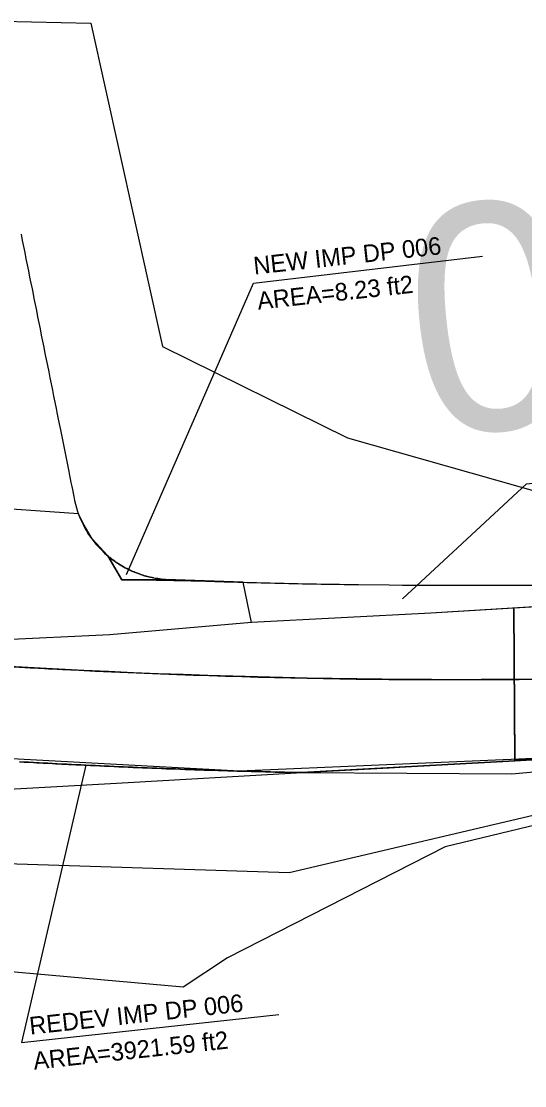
# Model space of a CAD drawing. Extents: x 1509538 to 1510847, y 401283 to 402022.
# Drawn here: x 1510556.6 to 1510636.5, y 401595.5 to 401764.5 of the extents above; entities that cross this region are included whole.
import ezdxf

# ---------------------------------------------------------------- set-up
doc = ezdxf.new("R2010")
doc.units = 0
for name, color, linetype in [('LDEFAULT_P', 7, 'Continuous'), ('Level 1', 7, 'Continuous'), ('Level 14', 7, 'Continuous'), ('Level 18', 7, 'Continuous'), ('Level 2', 7, 'Continuous'), ('Level 20', 7, 'Continuous'), ('Level 23', 7, 'Continuous'), ('Level 24', 7, 'Continuous'), ('Level 3', 7, 'Continuous'), ('Level 4', 7, 'Continuous')]:
    doc.layers.add(name, color=color, linetype=linetype)

msp = doc.modelspace()

# ---------------------------------------------------------------- linework, layer by layer
at = {"layer": 'LDEFAULT_P'}
for points in [[(1510573.25, 401676.67), (1510593.44, 401722.95), (1510629.75, 401727.21)], [(1510617.08, 401672.79), (1510636.74, 401691.05), (1510673.06, 401695.31)], [(1510566.79, 401646.37), (1510556.61, 401602.32), (1510597.45, 401606.77)]]:
    msp.add_lwpolyline(points, dxfattribs=at)
at = {"layer": 'Level 1'}
for p, q in [((1510634.73, 401671.34), (1510634.89, 401647.3)), ((1510634.89, 401647.08), (1510685.37, 401649.83)), ((1510634.89, 401647.3), (1510685.38, 401649.66))]:
    msp.add_line(p, q, dxfattribs=at)
for points in [[(1510684.15, 401674.32), (1510634.73, 401671.34)], [(1510684.29, 401671.55), (1510684.16, 401674.23), (1510634.73, 401671.34)], [(1510634.73, 401671.34), (1510634.89, 401647.08)]]:
    msp.add_lwpolyline(points, dxfattribs=at)
at = {"layer": 'Level 14'}
for p, q in [((1510556.53, 401730.7), (1510556.72, 401729.73)), ((1510556.72, 401729.73), (1510556.92, 401728.76)), ((1510556.92, 401728.76), (1510557.11, 401727.79)), ((1510557.11, 401727.79), (1510557.31, 401726.82)), ((1510557.31, 401726.82), (1510557.5, 401725.85)), ((1510557.5, 401725.85), (1510557.7, 401724.88)), ((1510557.7, 401724.88), (1510557.89, 401723.91)), ((1510557.89, 401723.91), (1510558.09, 401722.94)), ((1510558.09, 401722.94), (1510558.27, 401722.02)), ((1510558.27, 401722.02), (1510558.38, 401721.48)), ((1510558.38, 401721.48), (1510558.57, 401720.51)), ((1510558.57, 401720.51), (1510558.77, 401719.54)), ((1510558.77, 401719.54), (1510558.97, 401718.57)), ((1510558.97, 401718.57), (1510559.16, 401717.6)), ((1510559.16, 401717.6), (1510559.36, 401716.63)), ((1510559.36, 401716.63), (1510559.55, 401715.66)), ((1510559.55, 401715.66), (1510559.75, 401714.69)), ((1510559.75, 401714.69), (1510559.94, 401713.72)), ((1510559.94, 401713.72), (1510560.13, 401712.75)), ((1510560.13, 401712.75), (1510560.33, 401711.78)), ((1510560.33, 401711.78), (1510560.53, 401710.8)), ((1510560.53, 401710.8), (1510560.72, 401709.83)), ((1510560.72, 401709.83), (1510560.92, 401708.86)), ((1510560.92, 401708.86), (1510561.11, 401707.89)), ((1510561.11, 401707.89), (1510561.31, 401706.92)), ((1510561.31, 401706.92), (1510561.5, 401705.95)), ((1510561.5, 401705.95), (1510561.69, 401704.98)), ((1510561.69, 401704.98), (1510561.89, 401704.01)), ((1510561.89, 401704.01), (1510562.08, 401703.04)), ((1510562.08, 401703.04), (1510562.21, 401702.41)), ((1510562.21, 401702.41), (1510562.38, 401701.58)), ((1510562.38, 401701.58), (1510562.57, 401700.61)), ((1510562.57, 401700.61), (1510562.77, 401699.64)), ((1510562.77, 401699.64), (1510563.2, 401697.51)), ((1510563.2, 401697.51), (1510564.1, 401693)), ((1510564.1, 401693), (1510564.23, 401692.36)), ((1510564.23, 401692.36), (1510564.34, 401691.84)), ((1510564.34, 401691.84), (1510564.45, 401691.27)), ((1510564.45, 401691.27), (1510564.57, 401690.65)), ((1510564.57, 401690.65), (1510564.68, 401690.14)), ((1510564.68, 401690.14), (1510564.79, 401689.6)), ((1510564.79, 401689.6), (1510564.89, 401689.06)), ((1510564.89, 401689.06), (1510565.02, 401688.44)), ((1510565.02, 401688.44), (1510565.17, 401687.81)), ((1510565.17, 401687.81), (1510565.33, 401687.23)), ((1510565.33, 401687.23), (1510565.5, 401686.68)), ((1510565.5, 401686.68), (1510565.72, 401686.09)), ((1510565.72, 401686.09), (1510565.94, 401685.55)), ((1510565.94, 401685.55), (1510566.17, 401685.04)), ((1510566.17, 401685.04), (1510566.44, 401684.47)), ((1510566.44, 401684.47), (1510566.73, 401683.94)), ((1510566.73, 401683.94), (1510567.04, 401683.42)), ((1510567.04, 401683.42), (1510567.39, 401682.87)), ((1510567.39, 401682.87), (1510567.77, 401682.34)), ((1510567.77, 401682.34), (1510568.26, 401681.7)), ((1510568.26, 401681.7), (1510568.73, 401681.15)), ((1510568.73, 401681.15), (1510569.23, 401680.62)), ((1510569.23, 401680.62), (1510569.8, 401680.07)), ((1510569.8, 401680.07), (1510570.36, 401679.57)), ((1510570.36, 401679.57), (1510570.92, 401679.11)), ((1510570.92, 401679.11), (1510571.49, 401678.7)), ((1510571.49, 401678.7), (1510572, 401678.36)), ((1510572, 401678.36), (1510572.52, 401678.04)), ((1510572.52, 401678.04), (1510573.05, 401677.74)), ((1510573.05, 401677.74), (1510573.59, 401677.46)), ((1510573.59, 401677.46), (1510574.14, 401677.2)), ((1510574.14, 401677.2), (1510574.7, 401676.96)), ((1510574.7, 401676.96), (1510575.27, 401676.75)), ((1510575.27, 401676.75), (1510576.14, 401676.46)), ((1510576.14, 401676.46), (1510576.83, 401676.28)), ((1510576.83, 401676.28), (1510577.33, 401676.16)), ((1510577.33, 401676.16), (1510578.08, 401676.02)), ((1510578.08, 401676.02), (1510578.53, 401675.96)), ((1510578.53, 401675.96), (1510579.23, 401675.88)), ((1510579.23, 401675.88), (1510579.72, 401675.84)), ((1510579.72, 401675.84), (1510580.05, 401675.83)), ((1510580.05, 401675.83), (1510580.69, 401675.8)), ((1510580.69, 401675.8), (1510581.42, 401675.77)), ((1510581.42, 401675.77), (1510582.05, 401675.75)), ((1510582.05, 401675.75), (1510582.89, 401675.72)), ((1510582.89, 401675.72), (1510583.62, 401675.69)), ((1510583.62, 401675.69), (1510584.36, 401675.67)), ((1510584.36, 401675.67), (1510585.09, 401675.64)), ((1510585.09, 401675.64), (1510585.82, 401675.62)), ((1510585.82, 401675.62), (1510586.55, 401675.59)), ((1510586.55, 401675.59), (1510587.29, 401675.57)), ((1510587.29, 401675.57), (1510588.02, 401675.55)), ((1510588.02, 401675.55), (1510588.75, 401675.52)), ((1510588.75, 401675.52), (1510589.49, 401675.5)), ((1510589.49, 401675.5), (1510590.22, 401675.48)), ((1510590.22, 401675.48), (1510590.95, 401675.46)), ((1510590.95, 401675.46), (1510591.68, 401675.44)), ((1510591.68, 401675.44), (1510592.42, 401675.41)), ((1510592.42, 401675.41), (1510593.15, 401675.4)), ((1510593.15, 401675.4), (1510593.88, 401675.37)), ((1510593.88, 401675.37), (1510594.62, 401675.36)), ((1510594.62, 401675.36), (1510595.2, 401675.34)), ((1510595.2, 401675.34), (1510596.07, 401675.32)), ((1510596.07, 401675.32), (1510596.82, 401675.3)), ((1510596.82, 401675.3), (1510597.55, 401675.28)), ((1510597.55, 401675.28), (1510598.28, 401675.27)), ((1510598.28, 401675.27), (1510599.01, 401675.25)), ((1510599.01, 401675.25), (1510599.75, 401675.23)), ((1510599.75, 401675.23), (1510600.48, 401675.22)), ((1510600.48, 401675.22), (1510601.21, 401675.2)), ((1510601.21, 401675.2), (1510601.95, 401675.19)), ((1510601.95, 401675.19), (1510602.68, 401675.17)), ((1510602.68, 401675.17), (1510603.41, 401675.16)), ((1510603.41, 401675.16), (1510604.15, 401675.15)), ((1510604.15, 401675.15), (1510604.88, 401675.13)), ((1510604.88, 401675.13), (1510605.61, 401675.12)), ((1510605.61, 401675.12), (1510606.35, 401675.11)), ((1510606.35, 401675.11), (1510607.08, 401675.1)), ((1510607.08, 401675.1), (1510607.81, 401675.09)), ((1510607.81, 401675.09), (1510608.55, 401675.08)), ((1510608.55, 401675.08), (1510609.28, 401675.07)), ((1510609.28, 401675.07), (1510610.01, 401675.06)), ((1510610.01, 401675.06), (1510614.95, 401675)), ((1510614.95, 401675), (1510617.1, 401674.98)), ((1510617.1, 401674.98), (1510619.89, 401674.97)), ((1510619.89, 401674.97), (1510624.12, 401674.96)), ((1510624.12, 401674.96), (1510624.82, 401674.95)), ((1510624.82, 401674.95), (1510629.76, 401674.96)), ((1510629.76, 401674.96), (1510631.13, 401674.97)), ((1510631.13, 401674.97), (1510634.7, 401674.99)), ((1510634.7, 401674.99), (1510638.15, 401675.02))]:
    msp.add_line(p, q, dxfattribs=at)
for centre, radius, start, end in [((1510626.3, 402875.58), 1215.57, 260.85794, 272.75803), ((1510625.43, 402859.96), 1200, 264.92169, 266.98177)]:
    msp.add_arc(centre, radius, start, end, dxfattribs=at)
at = {"layer": 'Level 18'}
msp.add_line((1510570.63, 401667.06), (1510520.33, 401664.72), dxfattribs=at)
msp.add_lwpolyline([(1510671.73, 401673.2), (1510656.11, 401672.66), (1510621.58, 401670.53), (1510593.1, 401669.05), (1510570.63, 401667.06)], dxfattribs=at)
msp.add_arc((1510625.43, 402859.96), 1200, 264.92169, 272.83549, dxfattribs=at)
at = {"layer": 'Level 2'}
for p, q in [((1510634.73, 401671.34), (1510621.58, 401670.53)), ((1510634.89, 401647.08), (1510634.73, 401671.34)), ((1510556.28, 401646.92), (1510557.03, 401646.88)), ((1510558.53, 401646.8), (1510559.28, 401646.76)), ((1510560.78, 401646.68), (1510561.53, 401646.64)), ((1510561.53, 401646.64), (1510562.06, 401646.61)), ((1510569.79, 401646.23), (1510570.54, 401646.2)), ((1510570.54, 401646.2), (1510571.29, 401646.16)), ((1510571.29, 401646.16), (1510572.05, 401646.13)), ((1510573.55, 401646.06), (1510574.2, 401646.04)), ((1510574.2, 401646.04), (1510575.05, 401646)), ((1510601.13, 401645.2), (1510634.89, 401647.08)), ((1510622.45, 401646.41), (1510634.89, 401647.08)), ((1510575.05, 401646), (1510575.8, 401645.97)), ((1510575.8, 401645.97), (1510576.55, 401645.94)), ((1510576.55, 401645.94), (1510577.3, 401645.91)), ((1510580.31, 401645.79), (1510580.95, 401645.77)), ((1510580.95, 401645.77), (1510581.81, 401645.74)), ((1510583.31, 401645.68), (1510584.07, 401645.66)), ((1510584.07, 401645.66), (1510584.82, 401645.63)), ((1510584.82, 401645.63), (1510585.57, 401645.61)), ((1510585.57, 401645.61), (1510586.32, 401645.59)), ((1510587.82, 401645.54), (1510588.57, 401645.51)), ((1510588.57, 401645.51), (1510589.33, 401645.49)), ((1510589.33, 401645.49), (1510590.08, 401645.47)), ((1510594.44, 401645.35), (1510595.32, 401645.33)), ((1510600.6, 401645.21), (1510601.13, 401645.2))]:
    msp.add_line(p, q, dxfattribs=at)
for points in [[(1510621.58, 401670.53), (1510593.1, 401669.05), (1510591.76, 401675.43), (1510572.55, 401675.82), (1510570.33, 401679.6), (1510568.49, 401681.42), (1510567.15, 401683.24), (1510565.64, 401686.29), (1510548.91, 401687.45), (1510550.67, 401678.74), (1510543.3, 401672.37), (1510525.32, 401669.96), (1510520.33, 401664.72), (1510470.43, 401662.43), (1510425.8, 401661.46)], [(1510570.33, 401679.6), (1510567.82, 401682.33), (1510566.4, 401684.76), (1510565.64, 401686.29), (1510548.91, 401687.45), (1510550.67, 401678.74), (1510543.3, 401672.37), (1510525.32, 401669.96), (1510520.33, 401664.72)], [(1510621.58, 401670.53), (1510593.1, 401669.05), (1510591.76, 401675.43), (1510581.07, 401675.79), (1510572.55, 401675.82), (1510570.33, 401679.6)], [(1510634.89, 401647.08), (1510634.73, 401671.34), (1510621.58, 401670.53)], [(1510556.28, 401646.92), (1510557.03, 401646.88), (1510557.78, 401646.84), (1510558.53, 401646.8), (1510559.03, 401646.77), (1510559.28, 401646.76), (1510559.4, 401646.75), (1510560.03, 401646.72), (1510560.78, 401646.68), (1510561.53, 401646.64), (1510562.06, 401646.61), (1510562.28, 401646.6), (1510563.03, 401646.56), (1510563.78, 401646.52), (1510564.08, 401646.51), (1510564.54, 401646.48), (1510565.29, 401646.44), (1510566.04, 401646.41), (1510566.58, 401646.38), (1510566.79, 401646.37), (1510567.54, 401646.34), (1510568.29, 401646.3), (1510569.04, 401646.26), (1510569.14, 401646.26), (1510569.79, 401646.23), (1510570.54, 401646.2), (1510571.29, 401646.16), (1510572.05, 401646.13), (1510572.8, 401646.1), (1510573.55, 401646.06), (1510573.76, 401646.05), (1510574.2, 401646.04), (1510574.3, 401646.03), (1510575.05, 401646), (1510575.8, 401645.97), (1510576.55, 401645.94), (1510577.3, 401645.91), (1510578.06, 401645.88), (1510578.81, 401645.85), (1510579.26, 401645.83), (1510579.56, 401645.82), (1510580.31, 401645.79), (1510580.95, 401645.77), (1510581.06, 401645.77), (1510581.81, 401645.74), (1510582.56, 401645.71), (1510583.31, 401645.68), (1510584.07, 401645.66), (1510584.32, 401645.65), (1510584.82, 401645.63), (1510585.57, 401645.61), (1510586.32, 401645.59), (1510587.07, 401645.56), (1510587.82, 401645.54), (1510588.13, 401645.53), (1510588.57, 401645.51), (1510589.33, 401645.49), (1510589.38, 401645.49), (1510590.08, 401645.47), (1510590.83, 401645.45), (1510591.58, 401645.43), (1510592.33, 401645.41), (1510593.08, 401645.39), (1510593.84, 401645.37), (1510594.44, 401645.35), (1510594.59, 401645.35), (1510595.32, 401645.33), (1510595.34, 401645.33), (1510596.09, 401645.31), (1510596.84, 401645.29), (1510597.59, 401645.27), (1510598.35, 401645.26), (1510599.1, 401645.24), (1510599.5, 401645.23), (1510599.85, 401645.22), (1510600.6, 401645.21), (1510601.13, 401645.2)], [(1510557.03, 401646.88), (1510557.78, 401646.84), (1510558.53, 401646.8)], [(1510559.28, 401646.76), (1510560.03, 401646.72), (1510560.78, 401646.68)], [(1510562.06, 401646.61), (1510563.03, 401646.56), (1510563.78, 401646.52)], [(1510563.78, 401646.52), (1510564.54, 401646.48), (1510565.29, 401646.44), (1510566.04, 401646.41), (1510566.58, 401646.38)], [(1510566.58, 401646.38), (1510567.54, 401646.34), (1510568.29, 401646.3)], [(1510568.29, 401646.3), (1510569.04, 401646.26), (1510569.79, 401646.23)], [(1510572.05, 401646.13), (1510572.8, 401646.1), (1510573.55, 401646.06)], [(1510601.13, 401645.2), (1510614.95, 401645.98), (1510622.45, 401646.41)], [(1510577.3, 401645.91), (1510578.06, 401645.88), (1510578.81, 401645.85)], [(1510578.81, 401645.85), (1510579.56, 401645.82), (1510580.31, 401645.79)], [(1510581.81, 401645.74), (1510582.56, 401645.71), (1510583.31, 401645.68)], [(1510586.32, 401645.59), (1510587.07, 401645.56), (1510587.82, 401645.54)], [(1510590.08, 401645.47), (1510590.83, 401645.45), (1510591.58, 401645.43)], [(1510591.58, 401645.43), (1510592.33, 401645.41), (1510593.08, 401645.39), (1510593.84, 401645.37), (1510594.44, 401645.35)], [(1510595.32, 401645.33), (1510596.09, 401645.31), (1510596.84, 401645.29), (1510597.59, 401645.27), (1510598.35, 401645.26), (1510599.1, 401645.24), (1510599.85, 401645.22), (1510600.6, 401645.21)]]:
    msp.add_lwpolyline(points, dxfattribs=at)
at = {"layer": 'Level 20'}
for points in [[(1510601.13, 401645.2), (1510622.45, 401646.41), (1510672.72, 401649.13), (1510685.37, 401649.83)], [(1510556.28, 401646.92), (1510557.03, 401646.88), (1510557.78, 401646.84), (1510558.53, 401646.8), (1510559.03, 401646.77), (1510559.28, 401646.76), (1510559.4, 401646.75), (1510560.03, 401646.72), (1510560.78, 401646.68), (1510561.53, 401646.64), (1510562.06, 401646.61), (1510562.28, 401646.6), (1510563.03, 401646.56), (1510563.78, 401646.52), (1510564.08, 401646.51), (1510564.54, 401646.48), (1510565.29, 401646.44), (1510566.04, 401646.41), (1510566.58, 401646.38), (1510566.79, 401646.37), (1510567.54, 401646.34), (1510568.29, 401646.3), (1510569.04, 401646.26), (1510569.14, 401646.26), (1510569.79, 401646.23), (1510570.54, 401646.2), (1510571.29, 401646.16), (1510572.05, 401646.13), (1510572.8, 401646.1), (1510573.55, 401646.06), (1510573.76, 401646.05), (1510574.2, 401646.04), (1510574.3, 401646.03), (1510575.05, 401646), (1510575.8, 401645.97), (1510576.55, 401645.94), (1510577.3, 401645.91), (1510578.06, 401645.88), (1510578.81, 401645.85), (1510579.26, 401645.83), (1510579.56, 401645.82), (1510580.31, 401645.79), (1510580.95, 401645.77), (1510581.06, 401645.77), (1510581.81, 401645.74), (1510582.56, 401645.71), (1510583.31, 401645.68), (1510584.07, 401645.66), (1510584.32, 401645.65), (1510584.82, 401645.63), (1510585.57, 401645.61), (1510586.32, 401645.59), (1510587.07, 401645.56), (1510587.82, 401645.54), (1510588.13, 401645.53), (1510588.57, 401645.51), (1510589.33, 401645.49), (1510589.38, 401645.49), (1510590.08, 401645.47), (1510590.83, 401645.45), (1510591.58, 401645.43), (1510592.33, 401645.41), (1510593.08, 401645.39), (1510593.84, 401645.37), (1510594.44, 401645.35), (1510594.59, 401645.35), (1510595.32, 401645.33), (1510595.34, 401645.33), (1510596.09, 401645.31), (1510596.84, 401645.29), (1510597.59, 401645.27), (1510598.35, 401645.26), (1510599.1, 401645.24), (1510599.5, 401645.23), (1510599.85, 401645.22), (1510600.6, 401645.21), (1510601.13, 401645.2)]]:
    msp.add_lwpolyline(points, dxfattribs=at)
msp.add_arc((1510625.43, 402859.96), 1200, 264.92169, 272.83549, dxfattribs=at)
at = {"layer": 'Level 23'}
msp.add_lwpolyline([(1510410.25, 401663.98), (1510406.28, 401635.45), (1510599.09, 401629.32), (1510685.54, 401649.67), (1510635.53, 401647.32), (1510591.21, 401645.44), (1510529.65, 401648.74), (1510446.37, 401658.22)], close=True, dxfattribs=at)
at = {"layer": 'Level 24'}
msp.add_lwpolyline([(1510359.87, 401749.85), (1510436.07, 401732.12), (1510468.72, 401728.44), (1510492.07, 401724.89), (1510498.04, 401725.77), (1510520.27, 401739.91), (1510516.78, 401757.54), (1510553.49, 401764.52), (1510567.6, 401764.22), (1510578.98, 401712.86), (1510608.33, 401698.35), (1510682.71, 401677.22), (1510684.16, 401674.23), (1510685.11, 401648.19), (1510623.85, 401633.39), (1510589.3, 401615.77), (1510582.28, 401611.13), (1510485.41, 401619.76), (1510463.51, 401615.28), (1510452.26, 401619.93), (1510436.45, 401620.31), (1510422.96, 401609.85), (1510373.65, 401595.47)], dxfattribs=at)
at = {"layer": 'Level 3'}
for points in [[(1510581.07, 401675.79), (1510580.69, 401675.8), (1510580.4, 401675.81), (1510580.05, 401675.82), (1510580.05, 401675.83), (1510579.72, 401675.84), (1510579.44, 401675.86), (1510579.23, 401675.88), (1510579.13, 401675.89), (1510578.83, 401675.92), (1510578.53, 401675.96), (1510578.41, 401675.97), (1510578.23, 401676), (1510578.08, 401676.02), (1510577.93, 401676.05), (1510577.63, 401676.1), (1510577.6, 401676.11), (1510577.33, 401676.16), (1510577.03, 401676.23), (1510576.83, 401676.28), (1510576.8, 401676.28), (1510576.73, 401676.3), (1510576.44, 401676.38), (1510576.14, 401676.46), (1510576.01, 401676.5), (1510575.85, 401676.55), (1510575.77, 401676.58), (1510575.56, 401676.65), (1510575.27, 401676.75), (1510575.23, 401676.76), (1510574.99, 401676.85), (1510574.85, 401676.9), (1510574.7, 401676.96), (1510574.47, 401677.06), (1510574.42, 401677.08), (1510574.14, 401677.2), (1510574.04, 401677.25), (1510573.86, 401677.33), (1510573.72, 401677.4), (1510573.59, 401677.46), (1510573.32, 401677.6), (1510573.29, 401677.61), (1510573.05, 401677.74), (1510572.99, 401677.77), (1510572.78, 401677.89), (1510572.61, 401677.98), (1510572.52, 401678.04), (1510572.28, 401678.18), (1510572.26, 401678.2), (1510572, 401678.36), (1510571.99, 401678.37), (1510571.74, 401678.53), (1510571.59, 401678.63), (1510571.49, 401678.7), (1510571.41, 401678.76), (1510571.24, 401678.88), (1510571, 401679.06), (1510570.92, 401679.11), (1510570.87, 401679.16), (1510570.86, 401679.16), (1510570.76, 401679.24), (1510570.61, 401679.36), (1510570.52, 401679.44), (1510570.36, 401679.57), (1510570.33, 401679.6), (1510570.33, 401679.6), (1510572.55, 401675.82), (1510581.07, 401675.79)], [(1510591.76, 401675.43), (1510592.42, 401675.41), (1510593.15, 401675.4), (1510593.88, 401675.37), (1510594.62, 401675.36), (1510595.2, 401675.34), (1510595.35, 401675.34), (1510596.07, 401675.32), (1510596.08, 401675.32), (1510596.82, 401675.3), (1510597.55, 401675.28), (1510598.28, 401675.27), (1510599.01, 401675.25), (1510599.75, 401675.23), (1510600.14, 401675.22), (1510600.48, 401675.22), (1510601.21, 401675.2), (1510601.95, 401675.19), (1510602.68, 401675.17), (1510603.08, 401675.17), (1510603.41, 401675.16), (1510604.15, 401675.15), (1510604.88, 401675.13), (1510605.08, 401675.13), (1510605.61, 401675.12), (1510606.35, 401675.11), (1510607.08, 401675.1), (1510607.81, 401675.09), (1510608.55, 401675.08), (1510609.28, 401675.07), (1510610.01, 401675.06), (1510610.09, 401675.05), (1510614.95, 401675), (1510617.1, 401674.98), (1510619.89, 401674.97), (1510624.12, 401674.96), (1510624.82, 401674.95), (1510629.76, 401674.96), (1510631.13, 401674.97), (1510634.7, 401674.99), (1510680.3, 401674.33)], [(1510656.11, 401672.66), (1510621.58, 401670.53), (1510593.1, 401669.05), (1510591.76, 401675.43)]]:
    msp.add_lwpolyline(points, dxfattribs=at)
msp.add_lwpolyline([(1510601.12, 401645.2), (1510634.42, 401644.99), (1510685.38, 401649.66), (1510634.93, 401647.08)], close=True, dxfattribs=at)
at = {"layer": 'Level 4'}
for p, q in [((1510557.03, 401646.88), (1510556.28, 401646.92)), ((1510562.06, 401646.61), (1510561.53, 401646.64)), ((1510562.28, 401646.6), (1510562.06, 401646.61)), ((1510563.03, 401646.56), (1510562.28, 401646.6)), ((1510569.04, 401646.26), (1510568.29, 401646.3)), ((1510569.14, 401646.26), (1510569.04, 401646.26)), ((1510571.29, 401646.16), (1510570.54, 401646.2)), ((1510572.05, 401646.13), (1510571.29, 401646.16)), ((1510574.3, 401646.03), (1510574.2, 401646.04)), ((1510576.55, 401645.94), (1510575.8, 401645.97)), ((1510579.26, 401645.83), (1510578.81, 401645.85)), ((1510580.95, 401645.77), (1510580.31, 401645.79)), ((1510582.56, 401645.71), (1510581.81, 401645.74)), ((1510583.31, 401645.68), (1510582.56, 401645.71)), ((1510584.07, 401645.66), (1510583.31, 401645.68)), ((1510584.32, 401645.65), (1510584.07, 401645.66)), ((1510588.13, 401645.53), (1510587.82, 401645.54)), ((1510588.57, 401645.51), (1510588.13, 401645.53)), ((1510589.33, 401645.49), (1510588.57, 401645.51)), ((1510589.38, 401645.49), (1510589.33, 401645.49)), ((1510590.08, 401645.47), (1510589.38, 401645.49)), ((1510590.83, 401645.45), (1510590.08, 401645.47)), ((1510599.5, 401645.23), (1510599.1, 401645.24)), ((1510601.13, 401645.2), (1510600.6, 401645.21))]:
    msp.add_line(p, q, dxfattribs=at)
for points in [[(1510069.7, 401647.38), (1510070.82, 401637.95), (1510072.41, 401628.04), (1510122.3, 401634.81), (1510170.19, 401640.65), (1510220.23, 401643.86), (1510269.72, 401644.29), (1510320.63, 401641.42), (1510370.24, 401637.87), (1510421.73, 401637.03), (1510472.3, 401638.25), (1510523.24, 401640.81), (1510571.7, 401643.53), (1510601.13, 401645.2)], [(1510558.53, 401646.8), (1510557.78, 401646.84), (1510557.03, 401646.88)], [(1510559.28, 401646.76), (1510559.03, 401646.77), (1510558.53, 401646.8)], [(1510561.53, 401646.64), (1510560.78, 401646.68), (1510560.03, 401646.72), (1510559.4, 401646.75), (1510559.28, 401646.76)], [(1510564.08, 401646.51), (1510563.78, 401646.52), (1510563.03, 401646.56)], [(1510566.58, 401646.38), (1510566.04, 401646.41), (1510565.29, 401646.44), (1510564.54, 401646.48), (1510564.08, 401646.51)], [(1510568.29, 401646.3), (1510567.54, 401646.34), (1510566.79, 401646.37), (1510566.58, 401646.38)], [(1510570.54, 401646.2), (1510569.79, 401646.23), (1510569.14, 401646.26)], [(1510573.55, 401646.06), (1510572.8, 401646.1), (1510572.05, 401646.13)], [(1510574.2, 401646.04), (1510573.76, 401646.05), (1510573.55, 401646.06)], [(1510575.8, 401645.97), (1510575.05, 401646), (1510574.3, 401646.03)], [(1510578.81, 401645.85), (1510578.06, 401645.88), (1510577.3, 401645.91), (1510576.55, 401645.94)], [(1510580.31, 401645.79), (1510579.56, 401645.82), (1510579.26, 401645.83)], [(1510581.81, 401645.74), (1510581.06, 401645.77), (1510580.95, 401645.77)], [(1510585.57, 401645.61), (1510584.82, 401645.63), (1510584.32, 401645.65)], [(1510587.82, 401645.54), (1510587.07, 401645.56), (1510586.32, 401645.59), (1510585.57, 401645.61)], [(1510594.44, 401645.35), (1510593.84, 401645.37), (1510593.08, 401645.39), (1510592.33, 401645.41), (1510591.58, 401645.43), (1510590.83, 401645.45)], [(1510596.09, 401645.31), (1510595.34, 401645.33), (1510595.32, 401645.33), (1510594.59, 401645.35), (1510594.44, 401645.35)], [(1510599.1, 401645.24), (1510598.35, 401645.26), (1510597.59, 401645.27), (1510596.84, 401645.29), (1510596.09, 401645.31)], [(1510600.6, 401645.21), (1510599.85, 401645.22), (1510599.5, 401645.23)]]:
    msp.add_lwpolyline(points, dxfattribs=at)

# ---------------------------------------------------------------- texts
at = {"layer": 'LDEFAULT_P'}
for s, p in [('NEW IMP DP 006', (1510593.57, 401724.29)), ('AREA=8.23 ft2', (1510594.17, 401718.72)), ('REDEV IMP DP 006', (1510558, 401603.57)), ('AREA=3921.59 ft2', (1510558.61, 401598.01))]:
    msp.add_text(s, height=2.8, rotation=6.2219, dxfattribs=at).set_placement(p)
at = {"layer": 'Level 3'}
msp.add_text('006', height=36, rotation=6.2215, dxfattribs=at).set_placement((1510619.9, 401698.34))

doc.saveas('drawing.dxf')
